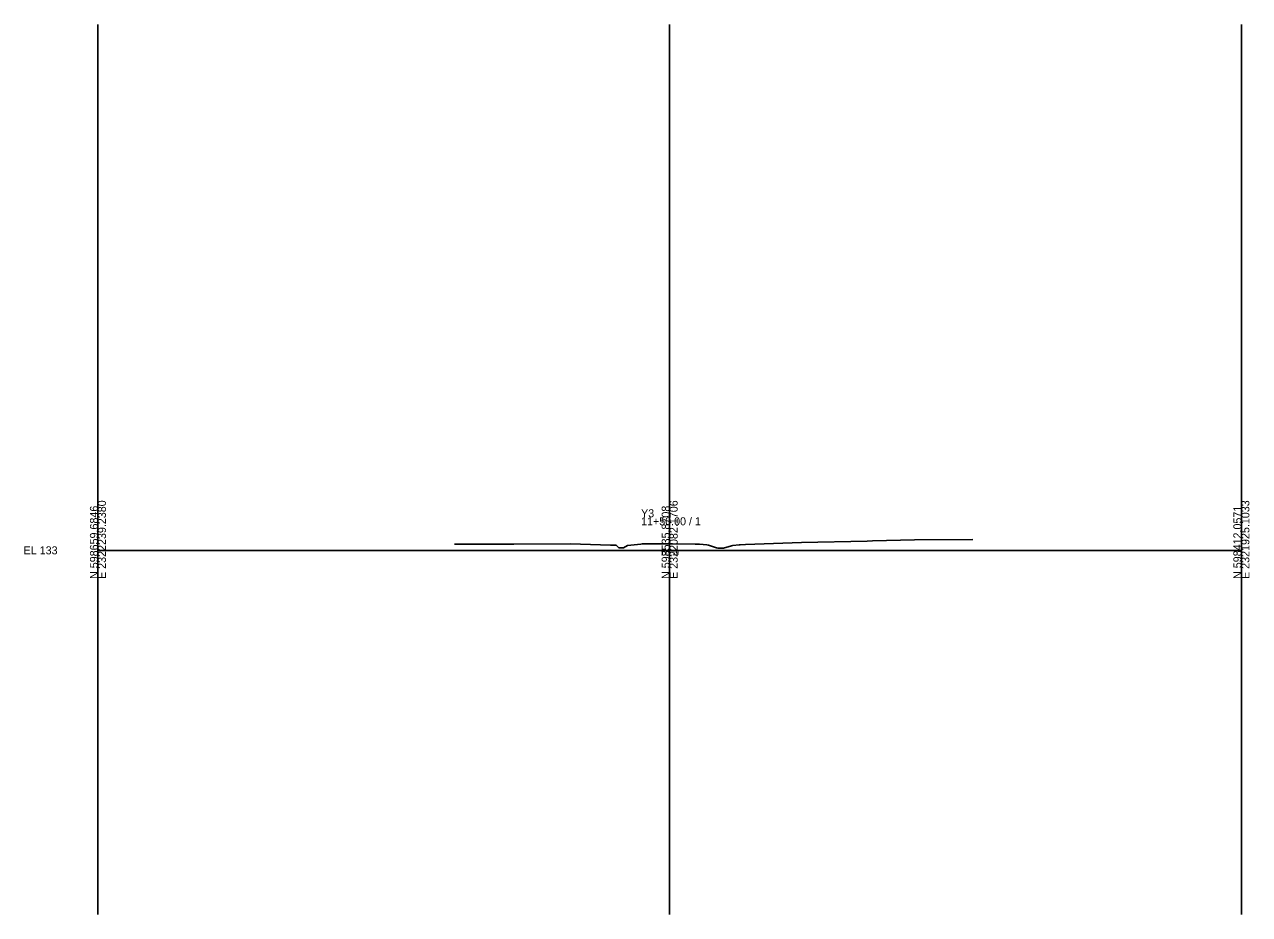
# Model space of a CAD drawing. Extents: x -26 to 7403, y 3373 to 4684.
# Drawn here: x 2774.3 to 3202.8, y 3372.7 to 3683.8 of the extents above; entities that cross this region are included whole.
import ezdxf

# ---------------------------------------------------------------- set-up
doc = ezdxf.new("R2010")
doc.units = 0
for name, color, linetype in [('Exist Cross Section Cell', 7, 'Continuous'), ('Exist XS Center Line Elevation Label', 7, 'Continuous'), ('Exist XS Ground Line', 7, 'Continuous'), ('Prop XS Exc Vertical Line 1', 7, 'Continuous'), ('Prop XS Exc Vertical Line 2', 7, 'Continuous'), ('Prop XS Exc Vertical Line 3', 7, 'Continuous')]:
    doc.layers.add(name, color=color, linetype=linetype)

msp = doc.modelspace()

# ---------------------------------------------------------------- linework, layer by layer
at = {"layer": 'Exist Cross Section Cell'}
for p, q in [((3000, 3500), (3000, 3511.56)), ((2800, 3500), (3000, 3500)), ((3000, 3500), (3200, 3500))]:
    msp.add_line(p, q, dxfattribs=at)
at = {"layer": 'Exist XS Ground Line'}
msp.add_lwpolyline([(2924.75, 3502.12), (2941.83, 3502.17), (2942.4, 3502.16), (2945.54, 3502.17), (2965.34, 3502.33), (2979.26, 3501.85), (2981.23, 3501.8), (2982.17, 3500.9), (2983.8, 3500.87), (2985.23, 3501.71), (2989.88, 3502.19), (2990.41, 3502.24), (2991.51, 3502.25), (3000, 3502.29), (3001.04, 3502.29), (3008.92, 3502.18), (3010.45, 3502.16), (3012.97, 3501.89), (3013.56, 3501.84), (3016.42, 3500.91), (3016.86, 3500.76), (3018.79, 3500.72), (3021.67, 3501.59), (3022.07, 3501.72), (3024.29, 3501.89), (3024.64, 3501.94), (3026.55, 3501.99), (3046.13, 3502.74), (3069.12, 3503.27), (3070.97, 3503.3), (3085.7, 3503.66), (3106.01, 3503.85)], dxfattribs=at)
at = {"layer": 'Prop XS Exc Vertical Line 1'}
msp.add_line((2800, 3683.81), (2800, 3372.72), dxfattribs=at)
at = {"layer": 'Prop XS Exc Vertical Line 2'}
msp.add_line((3000, 3683.81), (3000, 3372.72), dxfattribs=at)
at = {"layer": 'Prop XS Exc Vertical Line 3'}
msp.add_line((3200, 3683.81), (3200, 3372.72), dxfattribs=at)

# ---------------------------------------------------------------- texts
at = {"layer": 'Exist Cross Section Cell'}
for s, p in [('N 598659.6846', (2800, 3490)), ('E 2322239.2380', (2802.8, 3490)), ('N 598535.8708', (3000, 3490)), ('E 2322082.1706', (3002.8, 3490)), ('N 598412.0571', (3200, 3490)), ('E 2321925.1033', (3202.8, 3490))]:
    msp.add_text(s, height=2.8, rotation=90, dxfattribs=at).set_placement(p)
for s, p in [('Y3', (2990, 3511.56)), ('11+50.00 / 1', (2990, 3508.76)), ('EL 133', (2774, 3498.6))]:
    msp.add_text(s, height=2.8, dxfattribs=at).set_placement(p)
at = {"layer": 'Exist XS Center Line Elevation Label'}
msp.add_text('135.29', height=1.5, dxfattribs=at).set_placement((2996.94, 3498.29))

doc.saveas('drawing.dxf')
